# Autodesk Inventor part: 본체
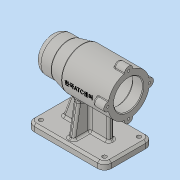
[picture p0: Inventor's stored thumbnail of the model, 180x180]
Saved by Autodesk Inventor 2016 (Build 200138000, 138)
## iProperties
Created: 2019-07
Part Number: 본체
Material: 일반
Document SubType Name: Modeling
Designer: Administrator
Density: 1 g/cm^3
Appearance: 기본값
Mass: 238.776 g
Surface Area: 654.818 cm^2
Volume: 238.776 cm^3
Author: Administrator
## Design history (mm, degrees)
sketch "스케치1"
  geometry: L1 (-56, -35)-(56, -35); L2 (56, -35)-(56, 35); L3 (56, 35)-(-56, 35); L4 (-56, 35)-(-56, -35); L5 (-56, -35)-(56, 35); L6 (56, -35)-(-56, 35); 1 further point
  constraints: 12 end point, 2 midpoint, 2 parallel, 1 horizontal, 1 perpendicular
  dimensions: "d0" = 112 distance of L3.end L2.end; "d1" = 70 distance of L2.end L1.end
extrude "돌출1" new body sketch "스케치1" distance "d2" = 10; taper "d3" = 0 deg
node "작업 평면1"
sketch "스케치2"
  geometry: L1 (56, 35)-(56, -35) reference; L2 (56, 0)-(-56, 0); L3 (-56, -35)-(-56, 35) reference; L4 (-56, 30)-(11, 30); L5 (11, 30)-(31, 25); L6 (31, 25)-(56, 25); L7 (56, 25)-(56, 0); L8 (-56, 30)-(-56, 0); 1 further point
  constraints: 12 end point, 2 midpoint, 2 perpendicular, 2 point on line, 1 collinear, 1 parallel
  dimensions: "d5" = 112 distance between parallel lines of L3 L7; "d6" = 25 distance of L5.end L6.end; "d7" = 45 horizontal distance of L4.end L6.end; "d8" = 50 diameter of L6 L2; "d9" = 60 diameter of L4 L2
revolve "회전1" sketch "스케치2" stored, may be unused: angle "d10" = 90 deg
sketch "스케치3"
  geometry: L1 (-4, 4)-(4, 4); L2 (4, 4)-(4, -4); L3 (4, -4)-(-4, -4); L4 (-4, -4)-(-4, 4); L5 (-4, 4)-(4, -4); L6 (4, 4)-(-4, -4); 1 further point
  constraints: 12 end point, 2 midpoint, 2 parallel, 1 horizontal, 1 perpendicular
  dimensions: "d11" = 8 distance of L2.end L3.end; "d12" = 8 distance of L1.end L2.end
extrude "돌출2" join sketch "스케치3" stored distance "d13" = 10; taper "d14" = 0 deg
sketch "스케치4"
  geometry: L1 (36, 10)-(-0.397, 110); L2 (-56, 10)-(56, 10) reference; L3 (-56, 110)-(11, 110) reference; L4 (56, 0)-(56, 10) reference; 1 further point
  constraints: 2 end point, 2 point on line
  dimensions: "d15" = 20 distance from line of L4 L1.start; "d16" = 110 deg angle of L2 L1
feature "리브1" sketch "스케치4" dims "d17" = 1, "d18" = 8, "d19" = 0, "d20" = 0, "d21" = 1, "d22" = 1
sketch "스케치5"
  geometry: L1 (-56, 10)-(56, 10) reference; L2 (-31, 10)-(-31, 110); L3 (-56, 110)-(11, 110) reference; L4 (-56, 0)-(-56, 10) reference; 1 further point
  constraints: 2 end point, 2 point on line, 1 perpendicular
  dimensions: "d23" = 25 distance from line of L4 L2.start
feature "리브2" sketch "스케치5" dims "d24" = 1, "d25" = 8, "d26" = 0, "d27" = 0, "d28" = 1, "d29" = 1
sketch "스케치6"
  geometry: L1 (35, 10)-(-35, 10) reference; L2 (-28, 10)-(-18.602, 63.298); L3 (-35, 0)-(-35, 10) reference; 1 further point
  constraints: 2 end point, 1 point on line, 2 other
  dimensions: "d31" = 7 distance from line of L3 L2.start; "d32" = 100 deg angle of L1 L2
feature "리브3" sketch "스케치6" dims "d33" = 1, "d34" = 8, "d35" = 0, "d36" = 0, "d37" = 1, "d38" = 1
sketch "스케치7"
  geometry: L1 (56, 35)-(56, -35) reference; L2 (56, 0)-(-56, 0); L3 (-56, -30)-(-56, 30) reference; L4 (-56, 0)-(-56, 21); L5 (-56, 21)-(-41, 21); L6 (-41, 21)-(-41, 21); L7 (-38, 24)-(10, 24); L8 (13, 21)-(13, 21); L9 (13, 21)-(24.7, 21); L10 (25, 20.7)-(25, 17.5); L11 (25, 17.5)-(42.7, 17.5); L12 (43, 17.2)-(43, 16); L13 (11, -30)-(11, 30) reference; L14 (43, 16)-(46.7, 16); L15 (47, 15.7)-(47, 10.5); L16 (47, 10.5)-(47, 10.5); L17 (50, 7.5)-(50, 0); A1 r 0.3 centre (46.7, 15.7) between (47, 15.7) and (46.7, 16); A2 r 0.3 centre (42.7, 17.2) between (43, 17.2) and (42.7, 17.5); A3 r 0.3 centre (24.7, 20.7) between (25, 20.7) and (24.7, 21); A4 r 3 centre (10, 21) between (13, 21) and (10, 24); A5 r 3 centre (-38, 21) between (-38, 24) and (-41, 21); A6 r 3 centre (47, 7.5) between (50, 7.5) and (47, 10.5); 8 further points
  constraints: 28 end point, 14 point on line, 12 point on circle, 12 tangent, 9 perpendicular, 6 centre point, 4 equal radius, 2 midpoint, 1 horizontal, 1 parallel
  dimensions: "d39" = 42 diameter of L5 L2; "d40" = 48 diameter of L7 L2; "d41" = 15 distance of L4.end L5.end; "d42" = 54 distance of point (-41, 24) point (13, 24); "d43" = 3 distance between parallel lines of L15 L17; "d44" = 4 distance between parallel lines of L12 L15; "d45" = 12 distance of L8.end point (25, 21); "d46" = 18 distance of L10.end point (43, 17.5); "d47" = 35 diameter of L11 L2; "d48" = 21 diameter of L16 L2; "d49" = 32 diameter of L14 L2; "d50" = 0.3 radius of A1; "d79" = 3 radius of A4
revolve "회전2" sketch "스케치7" stored, may be unused: angle "d51" = 90 deg
fillet "모깎기1" dims "d52" = 10
sketch "스케치9"
  geometry: C1 r 3 at (-46, 25); C2 r 3 at (46, 25); C3 r 3 at (46, -25); C4 r 3 at (-46, -25); A1 r 10 centre (-46, 25) between (-46, 35) and (-56, 25) reference; A2 r 10 centre (46, 25) between (56, 25) and (46, 35) reference; A3 r 10 centre (46, -25) between (46, -35) and (56, -25) reference; A4 r 10 centre (-46, -25) between (-56, -25) and (-46, -35) reference; 1 further point
  constraints: 4 centre point, 4 coincident
  dimensions: "d53" = 6 diameter of C1; "d54" = 6 diameter of C2; "d55" = 6 diameter of C3; "d56" = 6 diameter of C4
extrude "돌출3" cut sketch "스케치9" stored distance "d57" = 0; taper "d58" = 0 deg
sketch "스케치10"
  geometry: L1 (0, 0)-(-30, 0); C1 r 6 at (-30, 0); 1 further point
  constraints: 2 end point, 1 centre point, 1 coincident, 1 horizontal, 1 horizontal alignment, 1 other
  dimensions: "d59" = 12 diameter of C1
extrude "돌출4" join sketch "스케치10" distance "d60" = 16; taper "d61" = 0 deg
sketch "스케치11"
  geometry: A1 r 6 centre (0, 0) between (0.6, 5.97) and (0.6, -5.97) reference; A2 r 6 centre (30, 30) between (35.97, 29.4) and (24.03, 29.4) reference; 2 further points
  constraints: 1 coincident
hole "구멍1" sketch "스케치11" at (0, 0) diameter "d65" = 3.242; stored, may be unused: countersink angle "d69" = 90 deg, drill point angle "d71" = 118 deg; dims "d66" = 8, "d67" = 4, "d68" = 2, "d70" = 11
node "작업 평면2"
sketch "스케치12"
  geometry: L1 (56, 109.4)-(56, 85.97) reference; L2 (-56, 105)-(-56, 55) reference; L3 (-56, 80)-(56, 80); L4 (56, 81.621)-(56, 78.379) reference; 2 further points
  constraints: 2 end point, 2 midpoint, 1 point on line, 1 other
  dimensions: "d76" = 42 distance from line of L1 point (14, 80)
feature "엠보싱1" sketch "스케치12" dims "d0" = 112, "d1" = 70, "d77" = 0.5, "d78" = 0
chamfer "모따기1" distance "d80" = 3; stored, may be unused: second distance "d81" = 2, angle "d82" = 45 deg
fillet "모깎기3" dims "d84" = 10
fillet "모깎기5" dims "d86" = 3
fillet "모깎기6" dims "d87" = 3
fillet "모깎기7" dims "d88" = 3
fillet "모깎기8" dims "d89" = 3
fillet "모깎기9" dims "d90" = 1
fillet "모깎기10" dims "d91" = 3
chamfer "모따기2" distance "d92" = 1; stored, may be unused: second distance "d93" = 2, angle "d94" = 45 deg
node "솔리드1"
mirror "대칭1"
pattern_circular "원형 패턴1" dims angle "d63" = 360 deg
pattern_circular "원형 패턴2" dims angle "d73" = 360 deg
other parameters: "d75" = -228
